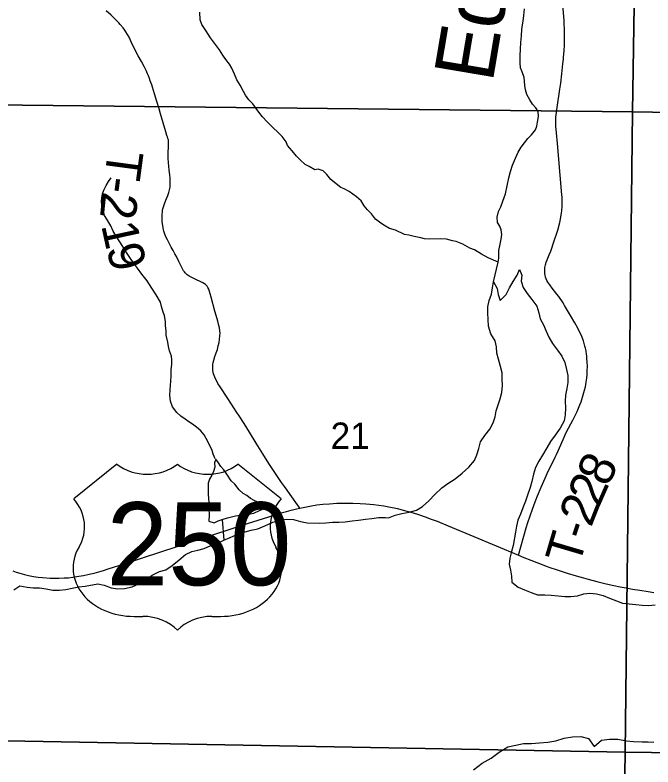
# Model space of a CAD drawing. Extents: x 0 to 34, y 0 to 22.
# Drawn here: x 20.261 to 21.275, y 16.628 to 17.822 of the extents above; entities that cross this region are included whole.
import ezdxf

# ---------------------------------------------------------------- set-up
doc = ezdxf.new("R2010")
doc.units = 0
for name, color, linetype in [('GM_X_Corporation', 7, 'Continuous'), ('GM_X_Major_Lake', 7, 'Continuous'), ('GM_X_Minor_River', 7, 'Continuous'), ('GM_X_Minor_River_Text', 7, 'Continuous'), ('GM_X_Section_Text', 7, 'Continuous'), ('GM_X_Township_Road', 7, 'Continuous'), ('GM_X_Township_Road_Text', 7, 'Continuous'), ('GM_X_US_Location', 7, 'Continuous'), ('GM_X_US_Route', 7, 'Continuous'), ('GM_X_US_Shield', 7, 'Continuous')]:
    doc.layers.add(name, color=color, linetype=linetype)

msp = doc.modelspace()

# ---------------------------------------------------------------- linework, layer by layer
at = {"layer": 'GM_X_Corporation'}
for points in [[(21.2582, 18.6819), (21.2422, 17.6682), (20.2237, 17.6792), (20.2437, 18.6978)], [(21.2582, 18.6819), (22.2749, 18.6656), (22.2529, 17.6514), (21.2422, 17.6682)], [(21.2422, 17.6682), (21.2309, 16.6512), (20.2179, 16.6698), (20.2237, 17.6792)], [(22.2529, 17.6514), (22.2392, 16.6385), (21.2309, 16.6512), (21.2422, 17.6682)], [(20.2179, 16.6698), (21.2309, 16.6512), (21.2159, 15.6439), (20.1931, 15.6647)], [(21.2309, 16.6512), (22.2392, 16.6385), (22.2224, 15.6282), (21.2159, 15.6439)]]:
    msp.add_lwpolyline(points, close=True, dxfattribs=at)
at = {"layer": 'GM_X_Major_Lake'}
for points in [[(20.8547, 17.0235), (20.8654, 17.0274), (20.8757, 17.0301), (20.8874, 17.0324), (20.8988, 17.0355), (20.9086, 17.0412), (20.9188, 17.0503), (20.9283, 17.0605), (20.9392, 17.0708), (20.9491, 17.0776), (20.9604, 17.0852), (20.9714, 17.0943), (20.982, 17.1038), (20.9911, 17.1141), (20.9952, 17.1236), (20.9979, 17.1335), (21.0009, 17.1441), (21.0077, 17.154), (21.0157, 17.1642), (21.0209, 17.1741), (21.0243, 17.1836), (21.0259, 17.193), (21.0289, 17.2029), (21.0319, 17.2124), (21.0349, 17.2226), (21.036, 17.2337), (21.0353, 17.2435), (21.0353, 17.2534), (21.0326, 17.2636), (21.0292, 17.2754), (21.0265, 17.2848), (21.0262, 17.2951), (21.0243, 17.3046), (21.0171, 17.3156), (21.0136, 17.3277), (21.0129, 17.3383), (21.0125, 17.3489), (21.0125, 17.3584), (21.0147, 17.3683), (21.0185, 17.3785), (21.0197, 17.3884), (21.0215, 17.3979), (21.0272, 17.3876), (21.0291, 17.3782), (21.0318, 17.3687), (21.0416, 17.3778), (21.0469, 17.3884), (21.0526, 17.3987), (21.059, 17.4086), (21.0628, 17.418), (21.0666, 17.4086), (21.0655, 17.3991), (21.0685, 17.3892), (21.0749, 17.3797), (21.0825, 17.3703), (21.0901, 17.3597), (21.0935, 17.349), (21.0958, 17.3396), (21.1007, 17.3297), (21.1053, 17.3198), (21.1094, 17.31), (21.1155, 17.3001), (21.1231, 17.2895), (21.1303, 17.2801), (21.1348, 17.2698), (21.1375, 17.2588), (21.1394, 17.2493), (21.1394, 17.2383), (21.1379, 17.2289), (21.136, 17.2182), (21.1356, 17.2087), (21.136, 17.1981), (21.1356, 17.1867), (21.1338, 17.1773), (21.1277, 17.1659), (21.1194, 17.1545), (21.1122, 17.1446), (21.1065, 17.1344), (21.0993, 17.123), (21.0937, 17.1131), (21.0884, 17.1032), (21.085, 17.0926), (21.0823, 17.0812), (21.0797, 17.0717), (21.0755, 17.0592), (21.0725, 17.0497), (21.068, 17.0391), (21.0646, 17.0292), (21.0604, 17.0197), (21.0582, 17.0099), (21.0566, 17.0004), (21.0525, 16.9795), (21.0502, 16.9696), (21.0476, 16.9594), (21.0465, 16.9499), (21.0484, 16.94), (21.0499, 16.9306), (21.0506, 16.9211), (21.0609, 16.9131), (21.0707, 16.909), (21.0813, 16.9048)], [(20.6126, 16.996), (20.6228, 17.0002), (20.636, 17.0036), (20.6466, 17.0059), (20.658, 17.0105), (20.6705, 17.0166), (20.6815, 17.0189), (20.6917, 17.0212), (20.7034, 17.0208), (20.7148, 17.0174), (20.7254, 17.0155), (20.7451, 17.0148), (20.7549, 17.0155), (20.7655, 17.0163), (20.7757, 17.0163), (20.7859, 17.0167), (20.7969, 17.0183), (20.8068, 17.0194), (20.8181, 17.0213), (20.8283, 17.0221), (20.8389, 17.0236), (20.8499, 17.0236), (20.8547, 17.0235)], [(20.2587, 16.9087), (20.2685, 16.9152), (20.2799, 16.9133), (20.2897, 16.9118), (20.2999, 16.9118), (20.3105, 16.9107), (20.3211, 16.9084), (20.3313, 16.9081), (20.3416, 16.9096), (20.3518, 16.9115), (20.3624, 16.9138), (20.3722, 16.9146), (20.3927, 16.9184), (20.4025, 16.9165), (20.4135, 16.912), (20.4241, 16.9105), (20.4347, 16.9108), (20.4472, 16.9135), (20.4585, 16.9192), (20.4684, 16.9245), (20.479, 16.9321), (20.4903, 16.9382), (20.5005, 16.9405), (20.5108, 16.9474), (20.5217, 16.9568), (20.532, 16.9648), (20.5418, 16.9698), (20.5516, 16.9721), (20.5615, 16.9747), (20.5721, 16.9793), (20.5819, 16.9827), (20.5929, 16.988), (20.6027, 16.9918), (20.6126, 16.996)], [(21.0813, 16.9048), (21.0915, 16.901), (21.1029, 16.901), (21.1131, 16.9003), (21.1241, 16.8992), (21.1347, 16.8981), (21.1445, 16.8984), (21.1548, 16.8996), (21.165, 16.9023), (21.1748, 16.9038), (21.1854, 16.9027), (21.1957, 16.9), (21.2059, 16.8959), (21.2169, 16.8913), (21.2267, 16.8879), (21.2373, 16.8864), (21.2475, 16.8857), (21.2577, 16.8846), (21.268, 16.8842), (21.2786, 16.885)], [(20.9898, 16.6231), (21.0037, 16.6335), (21.0176, 16.6416), (21.0304, 16.6512), (21.044, 16.6597), (21.0569, 16.6621), (21.069, 16.6649), (21.0818, 16.6646), (21.0947, 16.6659), (21.1076, 16.6668), (21.1208, 16.6688), (21.134, 16.6731), (21.1473, 16.6752), (21.1602, 16.676), (21.1723, 16.6728), (21.1815, 16.66), (21.1932, 16.6703), (21.206, 16.6716), (21.2189, 16.6717), (21.233, 16.6688), (21.244, 16.6682), (21.2576, 16.6675), (21.2671, 16.6673), (21.2766, 16.667)]]:
    msp.add_lwpolyline(points, dxfattribs=at)
at = {"layer": 'GM_X_Minor_River'}
msp.add_line((20.59, 17.0204), (20.5929, 16.988), dxfattribs=at)
for points in [[(21.029, 17.4294), (21.013, 17.4364), (21.0023, 17.4423), (20.9912, 17.449), (20.984, 17.4519), (20.9729, 17.4582), (20.9622, 17.4622), (20.9565, 17.4633), (20.947, 17.4658), (20.9372, 17.4664), (20.9194, 17.4662), (20.9118, 17.4664), (20.9057, 17.4682), (20.8951, 17.47), (20.8867, 17.4725), (20.8799, 17.4736), (20.8658, 17.4802), (20.8563, 17.4831), (20.8471, 17.4883), (20.8402, 17.4931), (20.8341, 17.4976), (20.8276, 17.5063), (20.8214, 17.5126), (20.8156, 17.519), (20.811, 17.5269), (20.8037, 17.5333), (20.7918, 17.5415), (20.7842, 17.5459), (20.7785, 17.5481), (20.7712, 17.5537), (20.7631, 17.5608), (20.7566, 17.5687), (20.7505, 17.5744), (20.7428, 17.5769), (20.7372, 17.5761), (20.7284, 17.5816), (20.7219, 17.5846), (20.7139, 17.5917), (20.7081, 17.5977), (20.7015, 17.606), (20.6942, 17.6146), (20.6919, 17.6203), (20.6857, 17.6289), (20.6795, 17.6346), (20.6699, 17.6439), (20.6615, 17.6522), (20.6542, 17.6601), (20.6484, 17.6676), (20.6441, 17.6736), (20.6387, 17.6808), (20.6326, 17.6871), (20.6272, 17.6947), (20.6241, 17.7007), (20.6186, 17.7105), (20.6136, 17.7192), (20.6096, 17.7283), (20.6053, 17.7377), (20.6018, 17.7438), (20.5957, 17.7513), (20.591, 17.7581), (20.586, 17.7667), (20.5794, 17.7754), (20.5717, 17.7859), (20.564, 17.7972), (20.5578, 17.8067), (20.5554, 17.8142), (20.5545, 17.8264)], [(21.0215, 17.3979), (21.029, 17.4294), (21.03, 17.4359), (21.0298, 17.4481), (21.032, 17.458), (21.0337, 17.466), (21.0348, 17.4736), (21.0339, 17.4808), (21.0315, 17.4865), (21.028, 17.4926), (21.0272, 17.5009), (21.0293, 17.5101), (21.033, 17.5174), (21.0363, 17.5262), (21.0403, 17.5377), (21.0431, 17.5506), (21.0459, 17.5632), (21.0484, 17.5732), (21.0517, 17.5835), (21.0565, 17.5946), (21.0609, 17.6042), (21.0657, 17.6123), (21.0709, 17.6192), (21.0761, 17.6257), (21.0817, 17.6319), (21.088, 17.6396), (21.0902, 17.6454), (21.0916, 17.6518), (21.093, 17.661), (21.0925, 17.6686), (21.0886, 17.6746), (21.0836, 17.6803), (21.0793, 17.6874), (21.0747, 17.6957), (21.0723, 17.7033), (21.0711, 17.7101), (21.0706, 17.717), (21.0701, 17.7227), (21.067, 17.7318), (21.0646, 17.7382), (21.0637, 17.7462), (21.0639, 17.7576), (21.0642, 17.7675), (21.0648, 17.7786), (21.0661, 17.7889), (21.0667, 17.7991), (21.0674, 17.8064), (21.0684, 17.8125), (21.0698, 17.8213), (21.0708, 17.8319)], [(20.5791, 17.1169), (20.576, 17.1245), (20.5744, 17.1302), (20.5717, 17.1362), (20.5647, 17.1491), (20.5616, 17.1551), (20.5562, 17.1615), (20.5493, 17.1675), (20.5428, 17.172), (20.537, 17.1757), (20.5313, 17.1802), (20.5244, 17.1846), (20.5179, 17.1906), (20.5113, 17.1997), (20.5082, 17.2084), (20.5069, 17.2179), (20.5075, 17.2266), (20.5078, 17.2339), (20.5085, 17.2403), (20.5091, 17.2491), (20.5093, 17.2582), (20.51, 17.2674), (20.5102, 17.2742), (20.5094, 17.2803), (20.5066, 17.2886), (20.505, 17.2955), (20.5038, 17.3023), (20.5013, 17.3133), (20.5009, 17.3205), (20.5, 17.3285), (20.4999, 17.3346), (20.4986, 17.3445), (20.4963, 17.3502), (20.4939, 17.3592), (20.4919, 17.3657), (20.4853, 17.3774), (20.4783, 17.3883), (20.4709, 17.3996), (20.4624, 17.4102), (20.4555, 17.42), (20.4493, 17.4286), (20.4443, 17.435), (20.4389, 17.4433), (20.4311, 17.4557), (20.4226, 17.4689), (20.4168, 17.4784), (20.4132, 17.4871), (20.407, 17.4976), (20.4032, 17.5033), (20.4008, 17.5112), (20.3988, 17.52), (20.3983, 17.5257), (20.3986, 17.5314), (20.4, 17.5379), (20.4022, 17.544), (20.4055, 17.5513), (20.4096, 17.5578), (20.4136, 17.5636)], [(20.5772, 17.0153), (20.5836, 17.0184), (20.59, 17.0204), (20.5987, 17.0232), (20.6051, 17.0248), (20.6111, 17.0265), (20.6217, 17.0281), (20.6289, 17.0286), (20.6349, 17.0295), (20.6406, 17.0307), (20.6496, 17.035), (20.6568, 17.0382), (20.6537, 17.0442), (20.6475, 17.0479), (20.6418, 17.0501), (20.635, 17.0542), (20.6292, 17.0587), (20.6235, 17.062), (20.6173, 17.068), (20.61, 17.0767), (20.6046, 17.0823), (20.5977, 17.0925), (20.5927, 17.0993), (20.588, 17.1049), (20.5842, 17.1105), (20.5799, 17.1166), (20.5781, 17.1105), (20.5782, 17.104), (20.5764, 17.0967), (20.5735, 17.091), (20.5698, 17.0848), (20.568, 17.0783), (20.5677, 17.0703), (20.5678, 17.0608), (20.5683, 17.054), (20.5688, 17.0475)], [(20.5688, 17.0475), (20.5688, 17.0378), (20.5695, 17.0279), (20.5687, 17.0181), (20.5772, 17.0153)]]:
    msp.add_lwpolyline(points, dxfattribs=at)
at = {"layer": 'GM_X_Township_Road'}
for points in [[(21.1688, 17.2872), (21.1686, 17.2884), (21.1678, 17.2926), (21.1669, 17.2962), (21.1658, 17.3003), (21.1645, 17.3045), (21.1634, 17.3071), (21.1612, 17.3127), (21.1573, 17.321), (21.1554, 17.3246), (21.1505, 17.3332), (21.144, 17.3445), (21.1346, 17.3606), (21.132, 17.3647), (21.1254, 17.3746), (21.1224, 17.3787), (21.1149, 17.3881), (21.1108, 17.3932), (21.1077, 17.3978), (21.1061, 17.4005), (21.1051, 17.403), (21.1043, 17.4056), (21.1037, 17.4086), (21.1033, 17.4112), (21.103, 17.4138), (21.1029, 17.4171), (21.1031, 17.4211), (21.1039, 17.425), (21.1045, 17.427), (21.1054, 17.4296), (21.1068, 17.4331), (21.108, 17.436), (21.1102, 17.4411), (21.1125, 17.4467), (21.1181, 17.4633), (21.1228, 17.4772), (21.1237, 17.4805), (21.1268, 17.4924), (21.1279, 17.4979), (21.1296, 17.5076), (21.13, 17.5107), (21.1306, 17.5182), (21.1307, 17.5217), (21.1304, 17.5326), (21.1302, 17.5363), (21.1248, 17.599), (21.1235, 17.6119), (21.1209, 17.6406), (21.1207, 17.6445), (21.1204, 17.6501), (21.1206, 17.66), (21.121, 17.6636), (21.1215, 17.6674), (21.1226, 17.6749), (21.127, 17.7042), (21.1283, 17.7137), (21.1299, 17.7284), (21.1317, 17.7445), (21.1326, 17.7521), (21.1329, 17.7557), (21.1332, 17.7594), (21.1337, 17.7661), (21.1341, 17.7738), (21.1343, 17.779), (21.1344, 17.7933), (21.1342, 17.8008), (21.134, 17.8068), (21.1337, 17.813), (21.1333, 17.8194), (21.1314, 17.8441)], [(20.5028, 17.629), (20.5022, 17.6305), (20.5004, 17.6364), (20.4923, 17.6653), (20.49, 17.6731), (20.4864, 17.6847), (20.4827, 17.6966), (20.4794, 17.7073), (20.4782, 17.7111), (20.4769, 17.715), (20.4759, 17.7177), (20.4747, 17.721), (20.4729, 17.7252), (20.4714, 17.7288), (20.4691, 17.7338), (20.4664, 17.7393), (20.4619, 17.748), (20.4567, 17.7571), (20.4535, 17.7632), (20.4513, 17.7675), (20.4487, 17.7727), (20.4457, 17.7792), (20.4421, 17.7869), (20.4395, 17.7913), (20.4371, 17.7953), (20.4355, 17.7979), (20.4329, 17.8015), (20.4281, 17.8071), (20.4259, 17.8094), (20.4199, 17.8153), (20.4135, 17.8216), (20.4056, 17.8289)], [(20.7134, 17.0388), (20.7125, 17.0401), (20.698, 17.0604), (20.6932, 17.0672), (20.6891, 17.073), (20.6845, 17.0796), (20.6802, 17.0859), (20.6748, 17.0937), (20.6686, 17.1031), (20.6643, 17.1097), (20.6546, 17.125), (20.6443, 17.1417), (20.6335, 17.1593), (20.625, 17.173), (20.617, 17.1854), (20.6136, 17.1907), (20.5993, 17.2127), (20.5868, 17.2311), (20.5834, 17.2369), (20.5815, 17.2401), (20.5797, 17.244), (20.5784, 17.2469), (20.5774, 17.2495), (20.5766, 17.252), (20.576, 17.2547), (20.5755, 17.2571), (20.5752, 17.2599), (20.5755, 17.2666), (20.576, 17.2701), (20.5768, 17.2736), (20.5786, 17.2793), (20.5806, 17.2852), (20.5825, 17.2909), (20.5839, 17.2965), (20.5853, 17.302), (20.586, 17.3071), (20.5866, 17.3122), (20.5867, 17.3164), (20.5863, 17.3204), (20.5857, 17.325), (20.5848, 17.3289), (20.5832, 17.3355), (20.5808, 17.3447), (20.5786, 17.3515), (20.5726, 17.3736), (20.5711, 17.3789), (20.57, 17.3828), (20.5687, 17.3865), (20.5674, 17.3893), (20.5662, 17.3913), (20.5652, 17.3926), (20.5636, 17.394), (20.562, 17.3951), (20.5594, 17.3966), (20.5453, 17.4033), (20.5378, 17.4072), (20.5347, 17.4092), (20.5329, 17.4109), (20.5313, 17.4124), (20.53, 17.4141), (20.5289, 17.4158), (20.5267, 17.4198), (20.5245, 17.4242), (20.5213, 17.4305), (20.5175, 17.4382), (20.515, 17.4429), (20.5123, 17.448), (20.5092, 17.4533), (20.5063, 17.4586), (20.5031, 17.4648), (20.5008, 17.4695), (20.499, 17.4738), (20.4974, 17.4784), (20.4968, 17.481), (20.4962, 17.4841), (20.4957, 17.4876), (20.4953, 17.4901), (20.4949, 17.494), (20.4947, 17.4973), (20.4946, 17.5029), (20.4947, 17.5058), (20.495, 17.5089), (20.4953, 17.5114), (20.496, 17.514), (20.4986, 17.5223), (20.5006, 17.5277), (20.5037, 17.5354), (20.5054, 17.5403), (20.5065, 17.5443), (20.5072, 17.5483), (20.5075, 17.5505), (20.5076, 17.5533), (20.5077, 17.5563), (20.5076, 17.5592), (20.5074, 17.5627), (20.5068, 17.5684), (20.506, 17.5757), (20.5053, 17.5817), (20.5048, 17.5872), (20.5044, 17.5945), (20.5043, 17.6015), (20.505, 17.6146), (20.5048, 17.6209), (20.5046, 17.6235), (20.5043, 17.6249), (20.5039, 17.6261), (20.503, 17.6283), (20.5028, 17.629)], [(21.061, 16.9639), (21.0735, 17.0074), (21.0761, 17.0157), (21.0797, 17.0263), (21.0835, 17.037), (21.0878, 17.0485), (21.0915, 17.058), (21.0972, 17.0719), (21.1037, 17.0865), (21.107, 17.0935), (21.1194, 17.1195), (21.1214, 17.1241), (21.1241, 17.1298), (21.1283, 17.139), (21.1338, 17.1514), (21.1372, 17.1586), (21.1443, 17.1727), (21.1474, 17.1783), (21.1534, 17.1899), (21.1545, 17.1922), (21.1568, 17.1977), (21.1588, 17.2027), (21.1606, 17.2076), (21.1642, 17.2189), (21.1662, 17.2259), (21.1675, 17.2316), (21.1689, 17.2386), (21.1698, 17.2451), (21.1703, 17.2512), (21.1706, 17.2568), (21.1707, 17.2641), (21.1704, 17.2705), (21.17, 17.2764), (21.1697, 17.2799), (21.1692, 17.2838), (21.1688, 17.2872)]]:
    msp.add_lwpolyline(points, dxfattribs=at)
at = {"layer": 'GM_X_US_Route'}
msp.add_lwpolyline([(20.2571, 16.9389), (20.2627, 16.937), (20.2684, 16.9353), (20.2758, 16.9334), (20.2824, 16.9319), (20.2904, 16.9303), (20.2975, 16.9291), (20.3045, 16.9284), (20.3167, 16.9275), (20.3245, 16.9272), (20.3306, 16.9274), (20.339, 16.9277), (20.3457, 16.9281), (20.3525, 16.929), (20.3624, 16.9304), (20.3696, 16.9318), (20.3785, 16.9337), (20.3864, 16.9356), (20.4017, 16.9398), (20.4089, 16.942), (20.4357, 16.9505), (20.6305, 17.0141), (20.6644, 17.0251), (20.6839, 17.0312), (20.6923, 17.0335), (20.6997, 17.0356), (20.7082, 17.0377), (20.7134, 17.0388), (20.7267, 17.0415), (20.7323, 17.0425), (20.7407, 17.0437), (20.7501, 17.0448), (20.7607, 17.0457), (20.7725, 17.0465), (20.7861, 17.0468), (20.7981, 17.0466), (20.8095, 17.0462), (20.8184, 17.0456), (20.831, 17.0444), (20.839, 17.0434), (20.8471, 17.0423), (20.8553, 17.0409), (20.8689, 17.0379), (20.8776, 17.0357), (20.8856, 17.0335), (20.8936, 17.0313), (20.9024, 17.0285), (20.9126, 17.0251), (20.9225, 17.0214), (20.932, 17.0178), (20.9494, 17.0108), (20.9901, 16.9936), (21.061, 16.9639), (21.0696, 16.9604), (21.0806, 16.9561), (21.0906, 16.9522), (21.0989, 16.9491), (21.1054, 16.9466), (21.1111, 16.9445), (21.1211, 16.9411), (21.1308, 16.9378), (21.1386, 16.9354), (21.1528, 16.9312), (21.1645, 16.9277), (21.1717, 16.9257), (21.1858, 16.922), (21.2005, 16.9184), (21.2129, 16.9157), (21.2226, 16.9137), (21.2323, 16.9119), (21.2424, 16.9101), (21.2542, 16.9082), (21.2672, 16.9061), (21.2765, 16.9048)], dxfattribs=at)
at = {"layer": 'GM_X_US_Shield'}
for p, q in [((20.4228, 17.1084), (20.3542, 17.0534)), ((20.6838, 17.0534), (20.6151, 17.1084)), ((20.4503, 16.8667), (20.464, 16.8667)), ((20.5739, 16.8667), (20.5876, 16.8667))]:
    msp.add_line(p, q, dxfattribs=at)
for centre, major_axis, start_param, end_param in [((20.4709, 17.1476), (-0.0687, 0), 0.795399, 2.346194), ((20.567, 17.1476), (-0.0687, 0), 0.795399, 2.346194), ((20.2754, 17.0093), (0.0961, 0), 5.838949, 6.894067), ((20.7625, 17.0093), (-0.0961, 0), 5.672304, 6.727422), ((20.4492, 16.9436), (0.0961, 0), 2.702327, 4.723529), ((20.5887, 16.9436), (-0.0961, 0), 1.559657, 3.580859), ((20.464, 16.8117), (-0.0687, 0), 3.785094, 4.712389), ((20.5739, 16.8117), (-0.0687, 0), 4.712389, 5.639684)]:
    msp.add_ellipse(centre, major_axis=major_axis, ratio=0.8, start_param=start_param, end_param=end_param, dxfattribs=at)

# ---------------------------------------------------------------- texts
at = {"layer": 'GM_X_Minor_River_Text'}
msp.add_text('Eddington', height=0.09468, rotation=80.4045, dxfattribs=at).set_placement((21.0198, 17.7131))
at = {"layer": 'GM_X_Section_Text'}
msp.add_text('21', height=0.04186, rotation=0, dxfattribs=at).set_placement((20.7625, 17.1328))
at = {"layer": 'GM_X_Township_Road_Text'}
for s, rotation, p in [('T', 262.4178, (20.4089, 17.6097)), ('-', 262.6125, (20.4033, 17.5673)), ('2', 264.1108, (20.4001, 17.5426)), ('1', 282.2914, (20.3976, 17.4882)), ('9', 284.4956, (20.4056, 17.4517)), ('8', 65.5112, (21.2033, 17.0708)), ('2', 66.1495, (21.1892, 17.0389)), ('2', 68.3329, (21.1765, 17.007)), ('-', 71.4663, (21.1694, 16.9856)), ('T', 73.5401, (21.1575, 16.9454))]:
    msp.add_text(s, height=0.0568, rotation=rotation, dxfattribs=at).set_placement(p)
at = {"layer": 'GM_X_US_Location'}
for s in ['0', '/']:
    msp.add_text(s, height=0.000189, dxfattribs=at).set_placement((20.5191, 16.9819))
msp.add_text('250', height=0.000189, rotation=0, dxfattribs=at).set_placement((20.4608, 16.9427))
at = {"layer": 'GM_X_US_Shield'}
msp.add_text('250', height=0.13184, dxfattribs=at).set_placement((20.4062, 16.9161))

doc.saveas('drawing.dxf')
